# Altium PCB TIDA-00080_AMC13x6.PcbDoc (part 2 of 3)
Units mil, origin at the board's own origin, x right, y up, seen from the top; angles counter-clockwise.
Board outline 7283.46 x 2559.06 mil, 4 copper layers (Top Layer, MidLayer1, MidLayer2, Bottom Layer), stack 61.2 mil thick; 372 components, 160 nets, 901 pads, 256 vias.
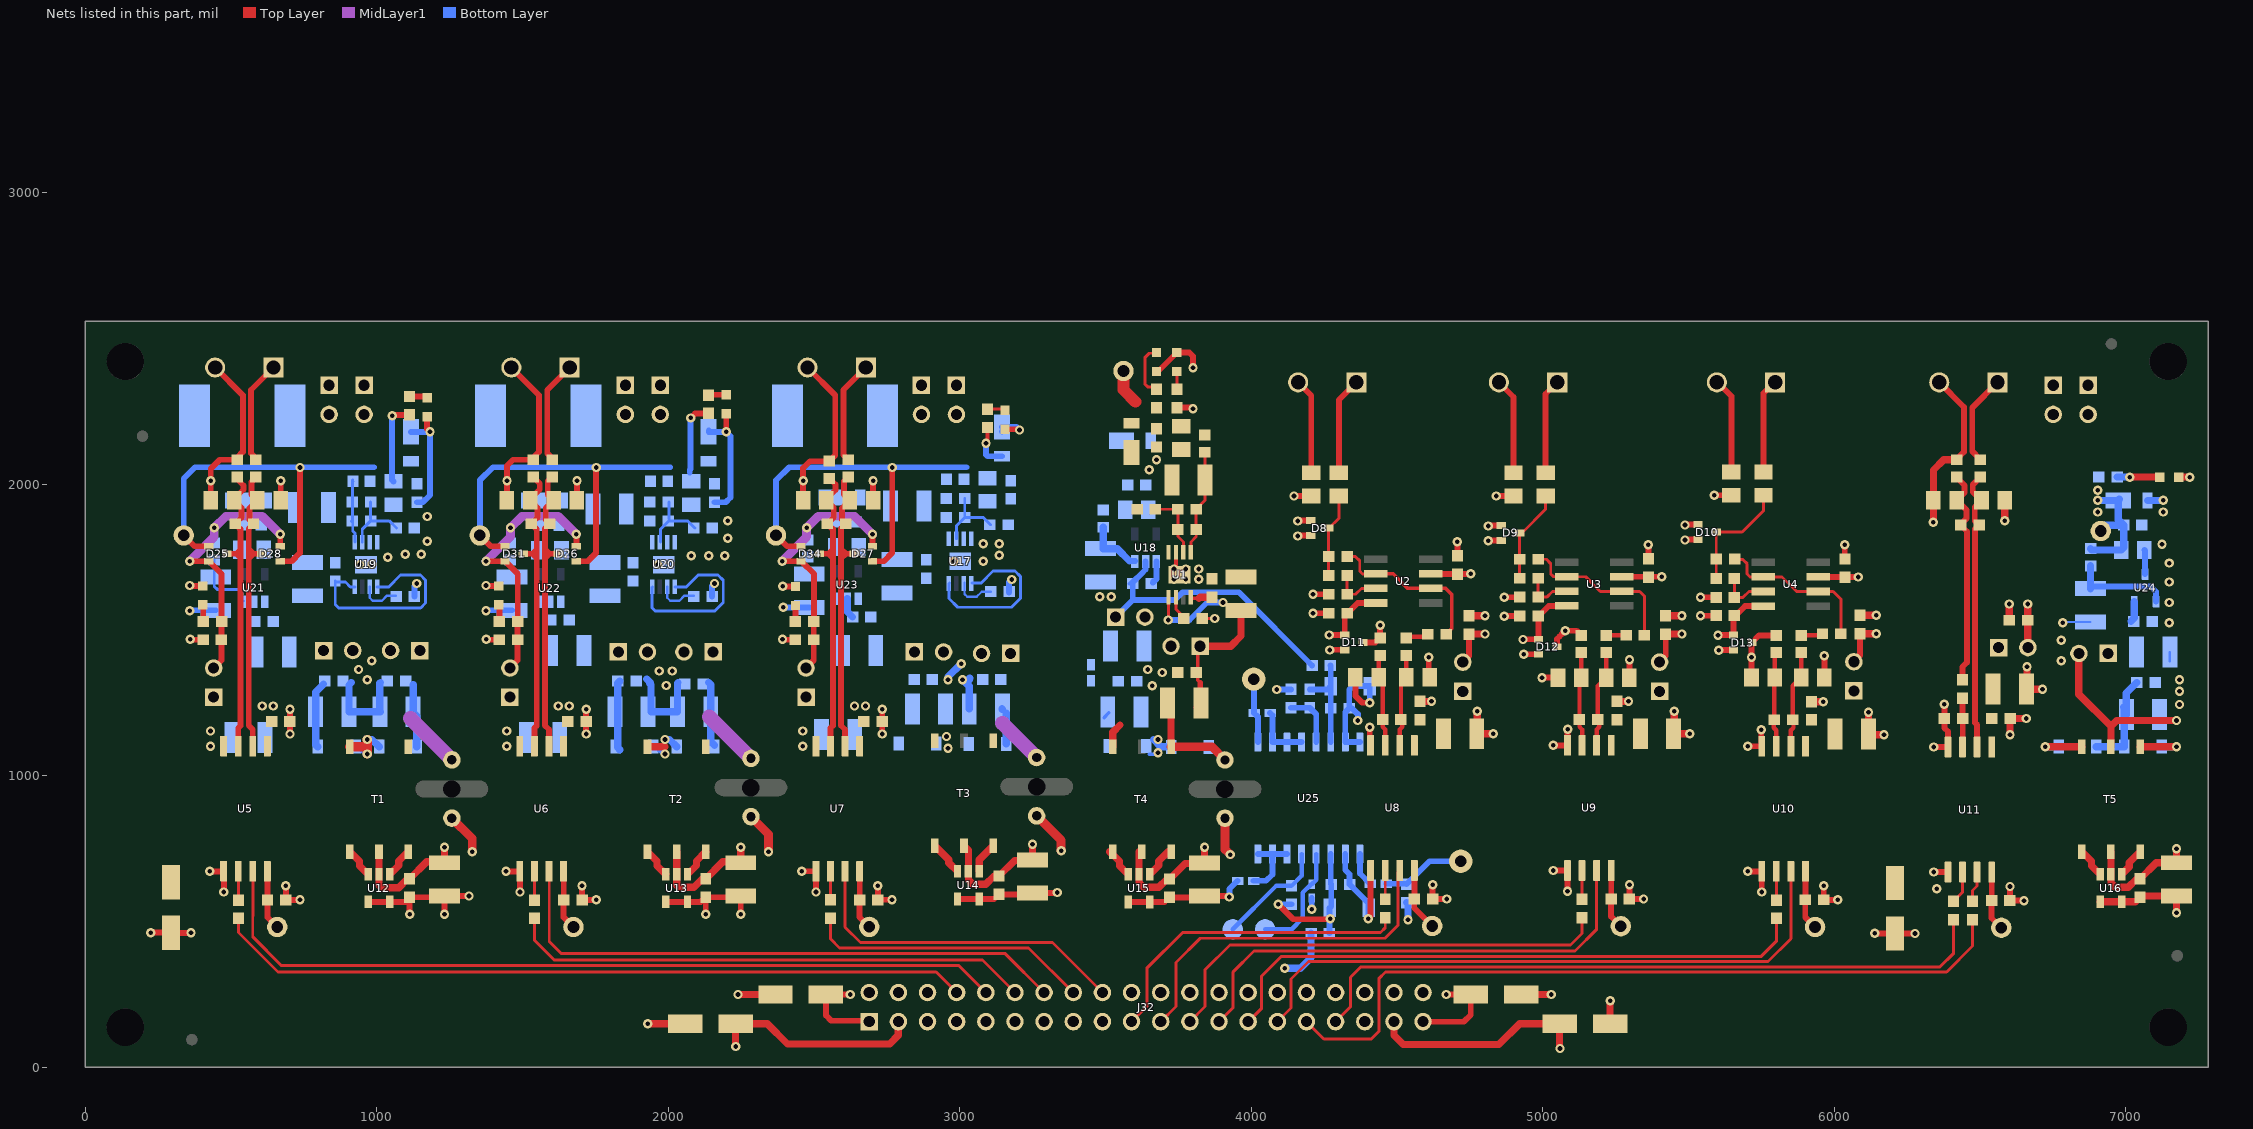
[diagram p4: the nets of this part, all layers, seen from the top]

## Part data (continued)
U12 U13 U14 U15 U16: "Transformer Driver for Isolated Power Supplies, DBV0005A", Alternate Manufacturer=None, Manufacturer="Texas Instruments"
U18 U21 U22 U23: "Regulator, LDO, 5V, 0.15A, SOT23-5", Alternate Manufacturer=None, Manufacturer="Texas Instruments"
U19: "-36V, -200mA, Ultralow-Noise, Negative Linear Regulator", Alternate Manufacturer=None, Manufacturer="Texas Instruments"
U24: library part CMP-0074892-1, "100-mA, 30-V, Fixed-Output, Linear-Voltage Regulator, DBZ0003A (SOT-23-3)", Alternate Manufacturer="Texas Instruments", Alternate PartNumber=TLV76050DBZT
U25: library part CMP-0081958-3, "500 mW, High-Efficiency, Low-Emissions, 5 kVRMS Isolated DC-DC Converter, DVE0016A (SO-MOD-16)", Alternate Manufacturer="Texas Instruments", Alternate PartNumber=UCC12050DVE, Operating Temperature Range="-40 to 125 C"
ZZ1: library part AssemblyNoteLabel, Alternate Manufacturer=-
ZZ2 ZZ3 ZZ4: library part AssemblyNote, Alternate Manufacturer=-

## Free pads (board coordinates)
  oval 250x60 hole 60 slot 250 at 0 deg unplated mask+10: 0(1258,955) 0(2284,960) 0(3264,963) 0(3910.2,954.72)

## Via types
v1: diameter 32, hole 16, Top Layer to Bottom Layer, tented both sides, 256 vias

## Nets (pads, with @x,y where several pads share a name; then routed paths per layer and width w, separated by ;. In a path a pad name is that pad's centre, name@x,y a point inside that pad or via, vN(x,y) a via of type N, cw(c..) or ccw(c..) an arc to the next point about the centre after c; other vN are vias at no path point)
+3.3V_DVDD: C61.2 C62.2 C63.2 C64.2 C65.2 C66.2 C67.2 C80.1 C81.1 J32.1 J32.39 TP6.1 TP7.1 TP8.1 TP9.1 TP10.1 TP11.1 TP12.1 U5.8 U6.8 U7.8 U8.8 U9.8 U10.8 U11.8 | length 2085.5
  Top Layer w20: U5.8@626,672.5 626,575 C61.2@625.5,574.5 625.5,515 TP6.1@659,481.5 ; U6.8@1642,672.5 1642,575 C62.2@1641.5,574.5 1641.5,515 TP7.1@1675,481.5 ; v1(2624.72,250) C80.1@2541.34,250 2541.34,178.39 2559.72,160 2686.43,160 J32.1@2689.73,156.69 ; U7.8@2656.99,672.87 2656.99,575.36 C66.2@2656.5,574.87 2656.5,515.36 TP8.1@2689.99,481.87 ; U8.8@4559.89,675.51 4559.89,578.01 C67.2@4559.39,577.51 4559.39,546.61 TP9.1@4621,485 ; J32.39@4589.73,156.69 4729.72,156.69 4753.11,180.08 C81.1@4753.11,250 v1(4669.72,250) ; U9.8@5235.19,675.51 5235.19,578.01 C63.2@5234.7,577.51 5234.7,518.01 TP10.1@5268.19,484.51 ; U10.8@5901.5,672.5 C64.2@5901.5,575 5901.01,574.5 5901.01,515 TP11.1@5934.5,481.5 ; U11.8@6540.45,670 6540.45,572.5 C65.2@6539.95,572 6539.95,512.5 TP12.1@6573.45,479
+5.0V_PH: C22.2 C24.2 C26.2 C36.1 C39.1 C42.1 C87.1 C95.2 D8.2 D9.2 D10.2 D11.2 D12.2 D13.2 D18.1 FB11.2 J28.2 J29.2 J30.2 R2.2 U2.7 U3.7 U4.7 | length 1247.5
  Top Layer w20: R2.2@3745.2,2263.23 3798.7,2263.23 3800.2,2264.72 v1(3800.2,2259.72) ; v1@4161.59,1824.41 D8.2@4204.5,1824.41 ; v1(4269.89,1431.83) 4270.48,1432.42 D11.2@4320.89,1432.42 D11.2@4323.39,1432.42 ; U2.7@4616.38,1693.01 v1(4753.38,1693.01) ; J28.2@4725.89,1390.01 4746.89,1411.01 C36.1@4746.89,1486.51 ; v1@4815.29,1807.8 D9.2@4858.2,1807.8 ; v1(4935.19,1416.83) 4935.78,1417.42 D12.2@4986.19,1417.42 ; D12.2@4985.6,1418.01 D12.2@4986.19,1417.42 ; D12.2@4988.7,1417.42 D12.2@4986.19,1417.42 ; U3.7@5271.69,1683.01 v1(5408.69,1683.01) ; J29.2@5401.19,1390.01 5422.19,1411.01 C39.1@5422.19,1486.51 ; v1@5489.61,1810.8 D10.2@5532.52,1810.8 ; v1(5604.01,1431.32) 5604.6,1431.91 D13.2@5655.01,1431.91 ; D13.2@5654.42,1432.5 D13.2@5655.01,1431.91 ; D13.2@5657.51,1431.91 D13.2@5655.01,1431.91 ; U4.7@5945.5,1682.5 v1(6082.5,1682.5) ; J30.2@6067.5,1391.5 6088.5,1412.5 C42.1@6088.5,1488.01
  Top Layer w25: C36.1@4746.38,1486.01 C36.1@4746.89,1486.51 v1(4802.39,1486.51) ; C39.1@5421.69,1486.01 5422.19,1486.51 v1(5477.7,1486.51) ; C42.1@6088,1487.5 C42.1@6088.5,1488.01 v1(6144.01,1488.01)
  other v1: 4813.79,1806.3 5488.11,1809.3 4160.09,1822.91
+5.0V_USH: C32.1 C96.1 C102.2 D21.1 D25.2 D28.2 FB12.2 J26.2 R28.2 | length 920.5
  Top Layer w20: v1(359,1736) 425,1736 468,1693 R28.2@468,1530 467.5,1529.5 C32.1@467.5,1467 467.5,1396.5 J26.2@441,1370 ; D28.2@668.99,1787.59 v1(669,1829)
  MidLayer1 w30: v1(359,1736) 443,1820 v1(443,1851) 483,1891 607,1891 v1(669,1829)
+5.0V_VDC: C45.1 C101.1 C106.2 D24.1 FB15.2 J31.2 R60.2 TP2.1 | length 576.4
  Top Layer w25: v1(6663.94,1589.5) C45.1@6663.94,1534 6664.45,1533.5 J31.2@6664.45,1440
  Bottom Layer w25: FB15.2@6879.45,1779.53 6883.98,1775 C106.2@6984.45,1775 6992.95,1783.5 C101.1@6992.95,1860 ; v1(6904.45,1945) D24.1@6974.25,1945 ; TP2.1@6929.45,1860 C101.1@6992.95,1860 ; D24.1@6977.95,1948.7 D24.1@6974.25,1945 ; D24.1@6974.25,1945 6974.25,1878.7 C101.1@6992.95,1860
  other v1: 6904.45,1905 6904.45,1980
+5.0V_VSH: C33.1 C98.1 C103.2 D22.1 D26.2 D31.2 FB13.2 J27.2 R30.2 | length 920.5
  Top Layer w20: v1(1375,1736) 1441,1736 1484,1693 R30.2@1484,1530 1483.49,1529.5 C33.1@1483.49,1467 1483.49,1396.5 J27.2@1457,1370 ; D26.2@1684.99,1787.59 v1(1685,1829)
  MidLayer1 w30: v1(1375,1736) 1459,1820 v1(1459,1851) 1499,1891 1623,1891 v1(1685,1829)
+5.0V_WSH: C34.1 C100.1 C104.2 D23.1 D27.2 D34.2 FB14.2 J22.2 R32.2 | length 920.5
  Top Layer w20: v1(2390.99,1736) 2456.99,1736 2499.99,1693 2499.99,1530 R32.2@2499.49,1529.5 C34.1@2499.49,1467 2499.49,1396.5 J22.2@2472.99,1370 ; D27.2@2700.98,1787.59 v1(2700.98,1828.99)
  MidLayer1 w30: v1(2390.99,1736) 2474.98,1819.99 v1(2474.98,1850.99) 2514.98,1890.99 2638.98,1890.99 v1(2700.98,1828.99)
+5V_CNTL: C68.1 C69.2 C70.2 C71.2 C72.2 C73.2 C74.2 C75.2 C76.2 C77.2 C78.2 C79.1 C82.1 C83.1 J32.3 J32.37 R33.2 R35.2 T1.2 T2.2 T3.2 T4.2 T5.2 U12.2 U13.2 U14.2 U15.2 U16.2 | length 4137.8
  Top Layer w20: v1(225,462.28) 293.61,462.28 C79.1@294.39,461.5 v1(363,461.5) ; v1(6139.45,459.77) 6208.06,459.77 C68.1@6208.45,459.39 6208.83,459 v1(6277.45,459)
  Top Layer w25: T1.2@1008,740 U12.2@1008,662.24 1008,625 1016.44,616.56 1075.85,616.56 1104.29,645 C71.2@1108,645 ; C71.2@1113,646.5 1171.5,705 C72.2@1233,705 ; C72.2@1233,702.09 C72.2@1233,705 ; v1(1233,755) C72.2@1233,705 ; T2.2@2029,740 U13.2@2029,662.24 2029,625 2035.91,618.09 2088.52,618.09 2116.92,646.5 C73.2@2129,646.5 2187.5,705 C74.2@2249,705 ; v1(2231.34,71.61) C82.1@2231.34,150 2339.72,150 2409.72,80 2759.72,80 2789.73,110.01 J32.3@2789.73,156.69 ; C74.2@2249,702.09 C74.2@2249,705 ; v1(2249,755) C74.2@2249,705 ; T3.2@3015,760 3030,745 U14.2@3030,672.24 3030,643.38 3045.28,628.09 3089.51,628.09 3117.92,656.5 C75.2@3131.49,656.5 ; C75.2@3135,660 C75.2@3131.49,656.5 ; C76.2@3250,710 3188.5,710 C75.2@3135,656.5 C75.2@3131.49,656.5 ; C76.2@3250,712.09 v1(3250,765) ; T4.2@3615.2,739.72 U15.2@3615.2,661.97 3615.2,634.72 3617.31,632.62 3617.31,630.99 3630.49,617.81 3683.29,617.81 3711.7,646.22 C77.2@3720.2,646.22 3773.7,699.72 C78.2@3840.2,699.72 ; C78.2@3840.2,701.81 v1(3840.2,754.72) ; J32.37@4489.73,156.69 4489.73,109.99 4521.34,78.39 4849.72,78.39 4921.34,150 C83.1@5058.11,150 5058.11,66.61 v1(5059.72,65) ; T5.2@6949.45,740 U16.2@6949.45,662.24 6949.45,633.38 6964.74,618.09 7008.97,618.09 7037.37,646.5 C69.2@7049.45,646.5 7105.04,702.09 C70.2@7174.45,702.09 v1(7174.45,750)
  Bottom Layer w25: v1@2229.72,70 v1(2231.34,71.61) ; v1(4115,340) 4169.35,340 4205.5,376.16 R33.2@4205.5,460 ; R35.2@4533,565.5 4538,560.5 v1(4538,507)
+6V_PH: C112.1 C125.2 J16.1 R31.1 R34.2 U18.2 | length 965.9
  Bottom Layer w12: C112.1@3582.6,1658.98 C112.1@3591.11,1667.48
  Bottom Layer w20: J16.1@3535.2,1544.72 3593.7,1603.23 ; C112.1@3593.7,1659.72 3593.7,1603.23 ; C112.1@3597.6,1667.48 3624.41,1694.29 3624.41,1694.46 3637.6,1707.65 U18.2@3637.6,1735.24 ; R34.2@4208.92,1379 3957.92,1630 3764.2,1630 3737.43,1603.23 3593.7,1603.23
+6V_USH: C114.1 C126.2 C127.1 C138.1 D29.1 J18.1 U21.2 | length 229.2
  Bottom Layer w25: D29.1@798,1100 790.91,1107.09 C138.1@790.91,1220 790.91,1287.91 C127.1@818,1315
+6V_VDC: C124.1 C135.1 C136.2 C145.1 D39.1 D40.1 J25.1 U24.2 | length 429.4
  Bottom Layer w25: D39.1@6898.92,1100 D40.1@6994.98,1100 6994.98,1232.38 C145.1@6992.36,1235 ; C145.1@7002.36,1210 7002.36,1284.41 C135.1@7037.95,1320 ; C124.1@7017.95,1530 7029.45,1541.5 U24.2@7029.45,1597.76
+6V_VSH: C118.1 C129.2 C137.1 C140.1 D32.1 J20.1 U22.2 | length 240.9
  Bottom Layer w25: D32.1@1834,1090 1826.91,1097.09 1826.91,1317.91 C137.1@1834,1325
+6V_WSH: C122.1 C131.2 C132.1 C142.1 D35.1 J23.1 U23.2 | length 70.4
  Bottom Layer w25: U23.2@2614,1608.02 2614,1563.77 C122.1@2632.5,1545.27
-5.0V_PH: C1.2 C2.1 C29.2 C30.2 C31.2 D6.2 D8.1 D9.1 D10.1 D11.1 D12.1 D13.1 FB1.2 R1.2 TP1.1 U2.4 U3.4 U4.4 | length 971.9
  Top Layer w20: v1@4161.59,1875.59 D8.1@4204.5,1875.59 ; v1(4267.38,1483.01) 4267.97,1483.6 D11.1@4320.89,1483.6 4320.89,1548.35 C29.2@4329.71,1557.17 ; C29.2@4328.88,1558.01 C29.2@4329.71,1557.17 ; U2.4@4427.38,1593.01 4365.55,1593.01 C29.2@4329.71,1557.17 ; v1@4815.29,1858.98 D9.1@4858.2,1858.98 ; v1(4932.69,1468.01) 4933.28,1468.6 D12.1@4986.19,1468.6 4986.19,1546 C30.2@4984.19,1548.01 4985.86,1548.01 5020.86,1583.01 U3.4@5082.69,1583.01 ; v1@5489.61,1861.98 D10.1@5532.52,1861.98 ; v1(5601.5,1482.5) 5602.09,1483.09 D13.1@5655.01,1483.09 C31.2@5655.01,1547.5 ; C31.2@5659.67,1547.5 5694.67,1582.5 U4.4@5756.5,1582.5
  Top Layer w40: TP1.1@3562,2389 3562,2325 3603,2284
  other v1: 4813.79,1857.48 5488.11,1860.48 4160.09,1874.09
-5.0V_USH: C89.1 C90.2 D19.2 D25.1 D28.1 FB9.2 R3.2 TP3.1 | length 1627
  Top Layer w20: TP3.1@338,1825 375.41,1787.59 D25.1@424.01,1787.59 ; D28.1@668.99,1736.41 708.41,1736.41 737,1765 v1(737,2058) ; v1(1053,2235) 1056.5,2238.5 R3.2@1113,2238.5
  Bottom Layer w20: TP3.1@338,1825 338,2020 377,2059 991,2059 ; v1(1053,2235) 1053,2015 C90.2@1058,2010
-5.0V_VSH: C92.2 C93.1 D20.2 D26.1 D31.1 FB10.2 R4.2 TP4.1 | length 1592.5
  Top Layer w20: TP4.1@1354,1825 1391.41,1787.59 D31.1@1440,1787.59 ; D26.1@1684.99,1736.41 1724.41,1736.41 1753,1765 v1(1753,2058) ; v1(2077,2228) 2092.5,2243.5 R4.2@2139,2243.5
  Bottom Layer w20: TP4.1@1354,1825 1354,2014 1399,2059 2007,2059 ; 2074,2040.2 2074,2050 2077,2053 v1(2077,2228)
-5.0V_WSH: C85.2 C86.1 D17.2 D27.1 D34.1 FB8.2 R5.2 TP5.1 | length 1488.6
  Top Layer w15: v1@3091.89,2140.1 3095.4,2143.61 R5.2@3095.4,2195.1
  Top Layer w20: TP5.1@2369.99,1825 2407.4,1787.59 D34.1@2456,1787.59 ; D27.1@2700.98,1736.41 2740.39,1736.4 2768.98,1764.99 v1(2768.98,2057.99)
  Bottom Layer w20: TP5.1@2369.99,1825 2369.99,2014 2415,2059 3022.99,2059 ; v1(3090.4,2141.6) 3090.4,2101.6 3095.59,2096.4 D17.2@3145.4,2096.4
-6V_PH: C20.1 C28.2 C35.2 C49.2 D38.2 J17.1 U1.5 U1.8 | length 824.9
  Top Layer w10: v1(3715.2,1534.72) 3716.4,1535.92 U1.5@3716.4,1613.12
  Top Layer w12: U1.8@3793.2,1613.12 3796.6,1609.72 3821.1,1609.72 3821.1,1610.62 ; 3825.2,1319.72 3817.29,1327.64 3817.29,1444.72 J17.1@3825.2,1444.72
  Top Layer w20: C49.2@3811.7,1234.72 3825.2,1248.23 3825.2,1319.72
  Top Layer w25: 3821.1,1609.72 3824.6,1613.23 C20.1@3865.2,1613.23 ; J17.1@3825.2,1444.72 3930.2,1444.72 3965.2,1479.72 C28.2@3965.2,1562.64
  Bottom Layer w12: 3835.2,1094.72 D38.2@3837.29,1096.81
  Bottom Layer w20: v1@3725.2,1534.72 3788.79,1534.72 3848.72,1594.65 v1(3903.5,1594.65)
-6V_USH: C107.2 C115.1 C128.2 C139.2 D30.2 J19.1 U19.5 U19.8 | length 963.8
  Bottom Layer w10: C115.1@858,1668.5 C115.1@858,1665 ; U19.8@925,1648.4 909.6,1648.4 893,1665 C115.1@858,1665 ; U19.5@1001.8,1648.4 1041.4,1648.4 1082,1689 1150.01,1689 1168,1671.01 1168,1593 1151,1576 870,1576 858,1588 C115.1@858,1665
  Bottom Layer w25: C139.2@1123,1220 1137.47,1205.53 D30.2@1137.47,1100 ; C139.2@1125.09,1220 1125.09,1312.91
-6V_VSH: C108.2 C119.1 C130.2 C141.2 D33.2 J21.1 U20.5 U20.8 | length 823.8
  Bottom Layer w10: U20.8@1946,1648.4 1944,1646.4 1944,1578 1957,1565 2159,1565 2189,1595 2189,1671.01 2171.01,1689 2103,1689 2062.4,1648.4 U20.5@2022.8,1648.4
  Bottom Layer w25: C130.2@2139,1320 2146.09,1312.91 C141.2@2146.09,1220 2146.09,1117.91 D33.2@2159,1105
-6V_WSH: C105.1 C109.2 C133.2 C143.2 D36.2 J24.1 U17.5 U17.8 | length 697.6
  Bottom Layer w10: U17.8@2965.2,1662 U17.8@2963.2,1660 2963.2,1608.6 2993.2,1578.6 3178.2,1578.6 3208.2,1608.6 3208.2,1684.61 3190.21,1702.6 3114.6,1702.6 3074,1662 U17.5@3042,1662
  Bottom Layer w25: C143.2@3145,1230 C143.2@3146.04,1228.96 ; D36.2@3159.46,1110 C143.2@3159.46,1215.53
CLKN_CH_U: J32.9
CLKN_CH_V: J32.13
CLKN_CH_W: J32.17
CLKN_U_PH: J32.22
CLKN_V_PH: J32.26
CLKN_VDC: J32.34
CLKN_W_PH: J32.30
CLKP_CH_U: J32.10 U5.7 | length 2971.8
  Top Layer w10: U5.7@575,672.87 575,448 674,349 2997.43,349 J32.10@3089.73,256.69 ; 576,519.5 U5.7@576,672.5
CLKP_CH_V: J32.14 U6.7 | length 2010.9
  Top Layer w10: U6.7@1592,672.5 1592,432 1634,390 3156.43,390 J32.14@3289.73,256.69
CLKP_CH_W: J32.18 U7.7 | length 1167.5
  Top Layer w10: U7.7@2606.99,672.87 2606.99,481.01 2660,428 3318.43,428 J32.18@3489.73,256.69
CLKP_U_PH: J32.21 U8.7 | length 1230.1
  Top Layer w10: J32.21@3689.73,156.69 3742,208.96 3742,360 3825,443 4459.37,443 4504,487.63 4504,669.63 U8.7@4509.89,675.51
CLKP_V_PH: J32.25 U9.7 | length 1700.2
  Top Layer w10: J32.25@3889.73,156.69 3937,203.96 3937,326 4010,399 5110.68,399 5185.19,473.51 U9.7@5185.19,675.51
CLKP_VDC: J32.33 R25.1 | length 2392.2
  Top Layer w10: J32.33@4289.73,156.69 4341,207.96 4341,309 4377,345 6363.45,345 6410,391.55 R25.1@6410,507.01
CLKP_W_PH: J32.29 U10.7 | length 2168.8
  Top Layer w10: J32.29@4089.73,156.69 4137,203.96 4137,303 4197,363 5773,363 5851.5,441.5 U10.7@5851.5,672.5
DGND: C57.1 C58.1 C59.1 C60.1 C61.1 C62.1 C63.1 C64.1 C65.1 C66.1 C67.1 C68.2 C69.1 C70.1 C71.1 C72.1 C73.1 C74.1 C75.1 C76.1 C77.1 C78.1 C79.2 C80.2 C81.2 C82.2 C83.2 C150.1 C154.2 J32.2 J32.4 J32.5 J32.6 J32.35 J32.36 J32.38 J32.40 R41.1 R44.2 U5.5 U6.5 U7.5 U8.5 U9.5 U10.5 U11.5 U12.4 U12.5 U13.4 U13.5 U14.4 U14.5 U15.4 U15.5 U16.4 U16.5 U25.2 | length 4763.7
  Top Layer w20: v1(427.5,672.5) 476,672.5 v1(476,601.5) ; v1(688.5,623.01) C61.1@688.5,574.5 v1(737,574.5) ; U12.4@970.6,567.76 U12.5@1045.4,567.76 1100.76,567.76 C71.1@1113,580 ; v1(1113,525) C71.1@1113,580 ; C72.1@1228,585 1226.5,583.5 C71.1@1113,583.5 C71.1@1113,580 ; v1(1233,525) C72.1@1233,587.91 1233.09,588 v1(1317,588) ; C72.1@1235.91,582.91 C72.1@1237.41,581.42 ; v1(1443.49,672.5) 1492,672.5 v1(1492,601.5) ; v1(1704.49,623.01) C62.1@1704.49,574.5 v1(1753,574.5) ; U13.4@1991.6,567.76 2061.24,567.76 U13.5@2064,565 ; U13.5@2066.4,567.76 2111.76,567.76 C73.1@2129,585 ; v1(2129,525) C73.1@2129,583.5 C74.1@2249,583.5 ; v1(2249,525) C74.1@2249,583.5 ; C74.1@2249,587.91 C74.1@2249,583.5 ; v1(2458.49,672.87) U7.5@2506.99,672.87 v1(2506.99,601.87) ; v1(2719.49,623.37) C66.1@2719.49,574.87 v1(2767.99,574.87) ; U14.4@2992.59,577.76 3062.75,577.76 U14.5@3065,580 ; U14.5@3067.4,577.76 3117.75,577.76 C75.1@3135,595 ; C75.1@3135,593.5 3253.5,593.5 C76.1@3255,595 ; C76.1@3250,597.91 3332.91,597.91 v1(3335,600) ; U15.4@3577.8,567.48 3647.96,567.48 U15.5@3650.2,569.72 ; U15.5@3652.6,567.48 3702.96,567.48 C77.1@3720.2,584.72 ; C77.1@3720.2,583.23 3838.7,583.23 C78.1@3840.2,584.72 ; C78.1@3840.2,587.64 3922.29,587.64 v1(3925.2,584.72) ; v1(4402,510) 4409.89,517.89 U8.5@4409.89,675.51 ; v1(4622.38,626.02) C67.1@4622.38,577.51 v1(4670.89,577.51) ; v1(5036.69,675.51) U9.5@5085.19,675.51 v1(5085.19,604.51) ; v1(5297.69,626.02) C63.1@5297.69,577.51 v1(5346.19,577.51) ; v1(5703,672.5) U10.5@5751.5,672.5 v1(5751.5,601.5) ; v1(5964,623.01) 5964,574.5 v1(6012.5,574.5) ; v1(6341.94,670) U11.5@6390.45,670 ; v1(6602.94,620.5) C65.1@6602.94,572 v1(6651.45,572)
  Top Layer w25: v1(1929.72,150) C82.2@2058.11,150 ; v1(2239.72,250) C80.2@2368.11,250 ; C81.2@4926.34,250 v1(5029.72,250) ; C83.2@5231.34,150 v1(5231.34,228.39) ; U16.4@6912.05,567.76 U16.5@6986.85,567.76 7033.7,567.76 C69.1@7049.45,583.5 7053.86,587.91 C70.1@7174.45,587.91 v1(7174.45,530)
  Top Layer w30: C57.1@1258,855 1328,785 v1(1328,740) ; C58.1@2284,860 2344,800 v1(2344,740) ; C59.1@3264,863 3348,779 v1(3348,743) ; C60.1@3910.2,854.72 3910.2,747.8 v1(3928,730)
  Bottom Layer w20: v1(3925.2,584.72) 3925.2,611.76 R44.2@3953.44,640 ; v1(4208,542) R41.1@4208,580.89 ; U25.2@4323,732.07 4323,677 4337.5,662.5 C150.1@4337.5,628 4402.93,562.57 C154.2@4402.93,547 4402.93,509.93 4402.86,510 v1(4402,510)
  other v1: 6352,613
DOUTN_CH_U: J32.7
DOUTN_CH_V: J32.11
DOUTN_CH_W: J32.15
DOUTN_U_PH: J32.20
DOUTN_V_PH: J32.24
DOUTN_VDC: J32.32
DOUTN_W_PH: J32.28
DOUTP_CH_U: J32.8 R39.2 | length 2597.2
  Top Layer w10: R39.2@526,511.01 526,463 662,327 2919.43,327 J32.8@2989.73,256.69
DOUTP_CH_V: J32.12 R42.2 | length 1797.6
  Top Layer w10: R42.2@1542,511.01 1542,435 1609,368 3078.43,368 J32.12@3189.73,256.69
DOUTP_CH_W: J32.16 R46.2 | length 979.4
  Top Layer w10: R46.2@2556.99,511.37 2556.99,441.01 2588,410 3236.43,410 J32.16@3389.73,256.69
DOUTP_U_PH: J32.19 R48.2 | length 1115.5
  Top Layer w10: J32.19@3589.73,156.69 3642,208.96 3642,340 3765,463 4444,463 4459.89,478.89 R48.2@4459.89,514.02
DOUTP_V_PH: J32.23 R51.2 | length 1599.2
  Top Layer w10: J32.23@3789.73,156.69 3842,208.96 3842,335 3927,420 5095.68,420 5135.19,459.51 R51.2@5135.19,514.02
DOUTP_VDC: J32.31 R58.2 | length 2638.5
  Top Layer w10: J32.31@4189.73,156.69 4249.23,97.19 4412.19,97.19 4438,123 4438,304 4461,327 6386,327 6475,416 R58.2@6475,506.5
DOUTP_W_PH: J32.27 R55.2 | length 2069
  Top Layer w10: J32.27@3989.73,156.69 4036,202.96 4036,313 4104,381 5750,381 5801.5,432.5 R55.2@5801.5,511.01
GND_PH: C1.1 C2.2 C9.1 C20.2 C21.2 C22.1 C23.2 C24.1 C25.2 C26.1 C27.1 C28.1 C29.1 C30.1 C31.1 C35.1 C36.2 C37.1 C38.1 C39.2 C40.1 C41.1 C42.2 C43.1 C44.1 C49.1 C50.2 C52.2 C54.2 C60.2 C87.2 C95.1 C111.1 C112.2 C125.1 C134.2 C144.2 C147.1 C148.1 C149.1 C152.1 C155.1 D1.2 D2.1 D6.1 D11.3 D12.3 D13.3 D18.2 FB19.1 FB21.1 FB23.1 J16.2 J17.2 R8.2 R11.2 R14.1 R19.2 R43.1 R45.1 T4.4 TP16.1 U1.3 U1.4 U1.9 U8.4 U9.4 U10.4 U18.1 U25.9 U25.15 U25.16 | length 3942.5
  Top Layer w10: C27.1@3831.7,1539.72 v1(3875.2,1539.72)
  Top Layer w15: U1.9@3742,1702.12 U1.3@3742,1766.72
  Top Layer w20: D1.2@3675.2,2387.24 3680.24,2387.24 D2.1@3745.2,2452.2 3787.72,2452.2 3800.2,2439.72 v1(3800.2,2399.72) ; U1.9@3742,1702.12 U1.9@3754.4,1689.72 ; v1(4147,1960) R8.2@4206,1960 R8.2@4208,1958 ; v1(4212.38,1558.01) C29.1@4265.89,1558.01 ; v1(4212.38,1623.01) C21.2@4265.89,1623.01 ; C37.1@4357.38,1338.01 4357.38,1274.62 4380.93,1251.07 v1(4406.93,1251.07) ; D11.3@4383.88,1458.01 4425.89,1458.01 FB19.1@4440.41,1472.54 ; v1(4407,1167) 4407,1107.53 U8.4@4409.89,1104.65 U8.4@4410.38,1105.14 ; v1(4442.38,1517.01) FB19.1@4442.38,1474.5 ; C38.1@4609.38,1346.01 v1(4609.38,1407.01) ; C22.1@4707.38,1754.5 v1(4707.38,1803.01) ; v1(4841,1960) R11.2@4900,1960 R11.2@4902,1958 ; v1(4867.69,1548.01) C30.1@4921.19,1548.01 ; v1(4867.69,1613.01) C23.2@4921.19,1613.01 ; v1(4997.69,1337.01) C40.1@5052.69,1337.01 C40.1@5052.69,1323.01 ; v1(5036.69,1104.65) U9.4@5085.19,1104.65 5085.69,1105.14 v1(5085.69,1160.01) ; D12.3@5049.19,1443.01 5049.19,1469.5 ; 5057.89,1478.21 5049.19,1469.5 ; FB21.1@5132.67,1481.8 5116.47,1498.01 v1(5077.69,1498.01) 5049.19,1469.5 ; C41.1@5297.69,1323.01 C41.1@5297.69,1337.01 v1(5297.69,1398.01) ; C24.1@5362.69,1744.5 v1(5362.69,1793.01) ; v1(5541.5,1549.5) C31.1@5595.01,1549.5 ; v1(5541.5,1612.5) C25.2@5595.01,1612.5 ; v1(5588.52,1962.5) R19.2@5647.52,1962.5 R19.2@5649.52,1960.5 ; v1(5703,1101.64) U10.4@5751.5,1101.64 5750,1103.14 v1(5750,1158) ; C43.1@5716.5,1337.5 v1(5716.5,1407.5) 5716.5,1457.5 D13.3@5717.25,1458.25 ; D13.3@5718,1457.5 5742.53,1482.03 FB23.1@5801.5,1482.03 ; C44.1@5966.5,1337.5 v1(5966.5,1412.5) ; C26.1@6036.5,1744 v1(6036.5,1792.5) ; FB19.1@4440.41,1472.54 FB19.1@4442.38,1474.5 ; FB19.1@4440.41,1472.54 FB19.1@4442.38,1472.54 FB19.1@4442.38,1474.5
  Top Layer w25: C49.1@3713.11,1249.72 3725.2,1237.64 T4.4@3725.2,1099.57 ; C50.2@4579.38,1255.5 v1(4618.89,1255.5) ; C36.2@4746.89,1549.5 v1(4802.39,1549.5) ; v1(4775.97,1221.3) 4775.97,1146.51 C147.1@4773.98,1144.52 v1@4829.49,1144.52 ; C52.2@5254.69,1255.5 v1(5294.19,1255.5) ; C39.2@5422.19,1549.5 v1(5477.7,1549.5) ; v1(5451.28,1221.3) 5451.28,1146.51 C148.1@5449.29,1144.52 v1(5504.79,1144.52) ; C54.2@5922.5,1255 5923,1254.5 v1(5962.5,1254.5) ; C42.2@6088.5,1551 v1(6144.01,1551) ; v1(6117.59,1218.29) C149.1@6117.59,1143.5 6115.6,1141.51 v1(6171.1,1141.51)
  Top Layer w30: T4.4@3725.2,1099.57 3865.36,1099.57 C60.2@3910.2,1054.72
  Bottom Layer w20: C112.2@3662.6,1662.48 C112.2@3664.1,1663.98 ; C112.2@3664.1,1667.48 C112.2@3664.1,1663.98 ; U18.1@3675,1735.24 3675,1674.88 C112.2@3664.1,1663.98 ; TP16.1@4009,1332 4009.88,1331.12 R45.1@4009.88,1216 4023,1202.88 U25.9@4023,1115.93 ; v1(4087.5,1296.5) R43.1@4137,1296.5 ; v1(4366,1190) 4366,1211.79 4345.79,1232 C152.1@4336.5,1232 ; U25.16@4373,1115.93 U25.15@4323,1115.93 4323,1218.5 C152.1@4336.5,1232 ; v1(4406.93,1251.07) C155.1@4406.93,1308 4349,1308 4336.5,1295.5 C152.1@4336.5,1232
  other v1: 4831,1144.52 3660.2,1309.72 3695.2,1354.72 3645.2,1364.72 3480.2,1614.72 3520.2,1614.72 3735.2,1674.72 3775.2,1674.72 3820.2,1674.72 3735.2,1709.72 3775.2,1709.72 3820.2,1709.72 3650.2,2049.72 3675.2,2084.72
GND_USH: C57.2 C88.1 C89.2 C90.1 C96.2 C102.1 C107.1 C113.1 C114.2 C115.2 C116.1 C126.1 C127.2 C128.1 C138.2 C139.1 D4.2 D14.1 D19.1 D21.2 J1.1 J1.2 J18.2 J19.2 R64.1 T1.4 U19.3 U19.4 U19.9 U21.1 | length 1089
  Top Layer w20: v1(359,1653) 360.52,1651.48 D14.1@403,1651.48 ; D4.2@1173,2232.52 1173,2190 v1(1183,2180)
  MidLayer1 w50: 1116,1197 C57.2@1258,1055
  Bottom Layer w20: v1@358.91,1567.91 C113.1@448,1567.91 ; D19.1@1118,2180.2 1182.8,2180.2 v1(1183,2180) 1183,1963 1158.5,1938.5 C89.2@1138,1938.5 ; C116.1@1129.5,1615 1129.5,1651.5 v1(1138,1660)
  Bottom Layer w25: 913,1320 905.09,1312.09 C138.2@905.09,1220 C139.1@1010.91,1220 ; C139.1@1013,1220 C139.1@1010.91,1220 ; 1013,1320 1010.91,1317.91 C139.1@1010.91,1220
  other v1: 968,1330 938,1365 983,1395 359,1566 943,1725 983,1725 1038,1750 1098,1760 1153,1760 1173,1805 1173,1890
GND_USH1: C3.1 C4.2 C17.1 C32.2 C46.2 FB3.1 J2.1 J2.2 J9.2 R20.1 U5.4 | length 780.4
  Top Layer w20: v1(360.5,1468.52) 362.02,1467 C32.2@404.5,1467 ; C3.1@431,1945 v1(431,2013) 431,2054 461.53,2084.53 FB3.1@521,2084.53 FB3.1@521,2091.5 ; J9.2@446,2401 541,2306 541,2111.5 FB3.1@521,2091.5 ; FB3.1@516,2086.5 FB3.1@521,2091.5 ; C4.2@671,1945 v1(671,2013) ; v1(702.5,1143.5) C46.2@702.5,1186 v1(702.5,1228.5)
  other v1: 430,1102 430,1154
GND_VDC: C101.2 C106.1 C123.1 C124.2 C135.2 C136.1 C145.2 D7.1 D24.2 J8.1 J8.2 J25.2 T5.5 U24.3 | length 903.4
  Top Layer w25: J25.2@6839.45,1420 6839.45,1280 6949.45,1170 ; T5.5@6949.45,1099.84 6949.45,1170 ; v1(7174.45,1190) 6969.45,1190 6949.45,1170 ; D7.1@7181.93,2025 v1(7219.45,2025)
  Bottom Layer w8: v1(6784.45,1525) 6787.36,1527.91 C123.1@6879.45,1527.91 ; C136.1@7151.54,1392.91 C136.1@7151.54,1425
  Bottom Layer w20: C106.1@7064.45,1775 7066.85,1772.6 U24.3@7066.85,1692.24
  Bottom Layer w25: D24.2@7074.65,1945 v1(7129.45,1945)
  other v1: 7184.45,1245 7184.45,1290 7184.45,1330 6779.45,1395 6779.45,1465 7149.45,1525 7149.45,1595 7149.45,1665 7149.45,1730 7124.45,1795 7129.45,1905
GND_VSH: C58.2 C91.1 C92.1 C93.2 C98.2 C103.1 C108.1 C117.1 C118.2 C119.2 C120.1 C129.1 C130.1 C137.2 C140.2 C141.1 D5.2 D15.1 D20.1 D22.2 J3.1 J3.2 J20.2 J21.2 R65.1 T2.4 U20.3 U20.4 U20.9 U22.1 | length 1123.8
  Top Layer w8: J20.2@1929,1400 J20.2@1929,1425
  Top Layer w20: v1(1375,1653) 1376.52,1651.48 D15.1@1419,1651.48 ; v1@2199,2195 D5.2@2199,2242.52
  MidLayer1 w50: 2140.5,1203.5 C58.2@2284,1060
  Bottom Layer w20: v1@1374.91,1567.91 C117.1@1464,1567.91 ; D20.1@2139,2185 D20.1@2139,2180.2 2198.8,2180.2 v1(2199,2180) 2214,2165 2214,1955 2197.5,1938.5 C93.2@2159,1938.5 ; C120.1@2150.5,1615 2150.5,1651.5 v1(2159,1660)
  Bottom Layer w25: 1926.91,1332.09 1939,1320 ; 1936.5,1317.5 1941.09,1312.91 1941.09,1220 C141.1@2031.91,1220 2031.91,1317.91 2034,1320
  other v1: 1994,1310 1969,1360 2014,1360 1375,1566 1964,1725 2079,1755 2139,1755 2194,1755 2204,1815 2204,1875
GND_VSH1: C5.1 C6.2 C18.1 C33.2 C47.2 FB5.1 J4.1 J4.2 J10.2 R22.1 U6.4 | length 772.3
  Top Layer w20: v1(1376.5,1468.52) 1378.02,1467 C33.2@1420.5,1467 ; C5.1@1447,1945 v1(1447,2013) 1447,2064 1467.53,2084.53 FB5.1@1537,2084.53 ; J10.2@1462,2401 1557,2306 1557,2111.5 FB5.1@1537,2091.5 ; C6.2@1687,1945 v1(1687,2013) ; v1(1718.49,1143.5) C47.2@1718.49,1186 v1(1718.49,1228.5)
  other v1: 1446,1102 1446,1154
GND_WSH: C59.2 C84.1 C85.1 C86.2 C100.2 C104.1 C105.2 C109.1 C110.1 C121.1 C122.2 C131.1 C132.2 C133.1 C142.2 C143.1 D3.2 D16.1 D17.1 D23.2 J5.1 J5.2 J23.2 J24.2 R63.1 T3.4 U17.3 U17.4 U17.9 U23.1 | length 664
  Top Layer w20: v1@2394.52,1649.47 D16.1@2437,1649.47 ; D3.2@3155.4,2189.12 3202.88,2189.12 v1(3205.4,2186.6)
  MidLayer1 w50: 3147,1180 C59.2@3264,1063
  Bottom Layer w20: v1(2394.91,1578.18) C121.1@2484,1578.18 ; D17.1@3145.4,2181.6 D17.1@3155.4,2191.6 ; D17.1@3145.4,2196.8 3195.2,2196.8 v1(3205.4,2186.6) ; C110.1@3169.69,1628.6 C110.1@3169.69,1631.9 3169.69,1665.1 v1(3178.2,1673.6)
  Bottom Layer w25: v1(2960,1330) 2960,1340 v1(3005,1385) ; v1(3010,1330) 3032.91,1307.09 C143.1@3032.91,1230 ; 3032.91,1330 3032.91,1332.91 3035,1335
  other v1: 2393,1650.99 2980.4,1736.6 3080.4,1736.6 3135.4,1756.6 3080.4,1796.6 3135.4,1796.6
GND_WSH1: C7.1 C8.2 C34.2 C48.2 C146.1 FB17.1 J6.1 J6.2 J11.2 R23.1 U7.4 | length 775.3
  Top Layer w20: v1@2394.02,1467 C34.2@2436.5,1467 ; C7.1@2462.99,1945 v1(2462.99,2013) 2462.99,2055.99 2486.53,2079.53 FB17.1@2552.99,2079.53 2572.99,2099.53 2572.99,2306 J11.2@2477.99,2401 ; C8.2@2702.99,1945 v1(2702.99,2013) ; v1(2734.49,1143.5) C48.2@2734.49,1186 v1(2734.49,1228.5)
  other v1: 2461.99,1102 2461.99,1154 2392.5,1468.52
GND_XSH1: C10.1 C11.2 C19.1 C45.2 C56.2 FB16.1 J7.1 J7.2 J15.2 R26.1 U11.4 | length 1154.5
  Top Layer w20: v1(6341.94,1099.13) U11.4@6390.45,1099.13 6390.45,1152 6378.01,1164.44 R26.1@6378.01,1196.8 v1(6378.01,1245.3) ; J15.2@6360.45,2350 6445.45,2265 6445.45,2111.5 6420.45,2086.5 FB16.1@6420.45,2084.53
  Top Layer w25: v1(6340.45,1870) C10.1@6340.45,1945 6340.45,2049.53 6375.45,2084.53 FB16.1@6420.45,2084.53 ; v1(6585.45,1875) C11.2@6585.45,1945 ; C45.2@6600.95,1534 v1(6600.95,1589.5) ; v1(6603.43,1141.3) C56.2@6603.43,1196.8 v1(6658.94,1196.8) ; v1(6661.45,1374) 6661.45,1299.21 C19.1@6659.46,1297.22 v1(6714.96,1297.22)
NetC3_2: C3.2 C12.2 D25.3 FB3.2 U5.3 | length 1062.4
  Top Layer w20: D25.3@487,1762 532,1762 533,1763 ; FB3.2@516,2023.5 543.2,1996.3 543.2,1982.2 511,1950 C3.2@511,1945 536,1920 536,1886.5 C12.2@514.5,1865 533,1846.5 533,1763 ; U5.3@525,1102 525,1164 533,1172 533,1763 ; 533,1748 519,1762 533,1776
NetC4_1: C4.1 C12.1 D28.3 FB2.2 U5.2 | length 1055.5
  Top Layer w20: 561,1746 577,1762 561,1778 ; 561,1762 D28.3@606,1762 ; U5.2@575,1102 575,1159 561,1173 561,1848.5 C12.1@577.5,1865 564,1878.5 564,1918 C4.1@591,1945 571.2,1964.8 571.2,2008.7 FB2.2@586,2023.5
NetC5_2: C5.2 C13.2 D31.3 FB5.2 U6.3 | length 1064.4
  Top Layer w20: D31.3@1503,1762 1548,1762 1549,1763 ; FB5.2@1532,2023.5 FB5.2@1533.51,2021.99 ; FB5.2@1537,2025.47 1559.2,2003.27 1559.2,1982.2 1527,1950 C5.2@1527,1945 1552,1920 1552,1886.5 C13.2@1530.5,1865 1549,1846.5 1549,1763 ; U6.3@1541,1102 1541,1164 1549,1172 1549,1763 ; 1549,1748 1535,1762 1549,1776
NetC6_1: C6.1 C13.1 D26.3 FB4.2 U6.2 | length 1059.6
  Top Layer w20: 1577,1746 1593,1762 1577,1778 ; 1577,1762 D26.3@1622,1762 ; U6.2@1591,1102 1591,1159 1577,1173 1577,1848.5 C13.1@1593.49,1865 1580,1878.5 1580,1918 C6.1@1607,1945 1587.2,1964.8 1587.2,2010.67 FB4.2@1602,2025.47 ; FB4.2@1600.48,2021.99 FB4.2@1602,2023.5
NetC7_2: C7.2 C14.2 D34.3 FB17.2 U7.3 | length 1061.9
  Top Layer w20: D34.3@2518.99,1762 2563.99,1762 2564.99,1763 ; FB17.2@2547.99,2023.5 FB17.2@2552.01,2019.49 ; FB17.2@2552.99,2020.47 2574,1999.47 2574,1981.01 2542.99,1950 C7.2@2542.99,1945 2567.99,1920 2567.99,1886.5 C14.2@2546.5,1865 2564.99,1846.5 2564.99,1763 ; U7.3@2556.99,1102 2556.99,1164 2564.99,1172 2564.99,1763 ; 2564.99,1748 2550.99,1762 2564.99,1776
NetC8_1: C8.1 C14.1 D27.3 FB7.2 U7.2 | length 1057.5
  Top Layer w20: 2592.99,1746 2608.99,1762 2592.99,1778 ; 2592.99,1762 D27.3@2637.99,1762 ; U7.2@2606.99,1102 2606.99,1159 2592.99,1173 2592.99,1848.5 C14.1@2609.49,1865 2595.99,1878.5 2595.99,1918 C8.1@2622.99,1945 2603.19,1964.8 2603.19,2010.67 FB7.2@2617.99,2025.47
NetC9_2: C9.2 C15.2 FB1.1 R15.2 U1.1 | length 362.5
  Top Layer w10: U1.1@3793.2,1766.72 3793.2,1802.72 3811.7,1821.22 C15.2@3811.7,1844.72 ; C15.2@3810.2,1844.72 3810.2,1913.23 R15.2@3811.7,1914.72 ; R15.2@3810.2,1914.72 3842.29,1946.81 C9.2@3842.29,2014.72 FB1.1@3842.29,2107.64
NetC10_2: C10.2 C16.2 FB16.2 R29.2 | length 756.4
  Top Layer w20: FB16.2@6420.45,2025.47 6420.45,2023.5 6447.65,1996.3 6447.65,1972.2 C10.2@6420.45,1945 6454.45,1911 6454.45,1884 6433.95,1863.5 C16.2@6433.95,1860 6455.45,1838.5 6455.45,1389.45 6440,1374 R29.2@6440,1329.5
NetC11_1: C11.1 C16.1 FB6.2 U11.2 | length 971
  Top Layer w20: U11.2@6490.45,1099.13 6490.45,1175 6483.45,1182 6483.45,1846.5 C16.1@6496.94,1860 6482.45,1874.5 6482.45,1922 C11.1@6505.45,1945 6475.65,1974.8 6475.65,1998.7 FB6.2@6500.45,2023.5
NetC15_1: C15.1 R14.2 R15.1 U1.2 | length 235
  Top Layer w10: R14.2@3670.2,1914.72 R14.2@3671.7,1914.72 R15.1@3748.7,1914.72 3748.7,1846.22 C15.1@3750.2,1844.72 ; C15.1@3748.7,1844.72 3748.7,1821.22 3767.6,1802.32 U1.2@3767.6,1766.72
NetC17_2: C17.2 C46.1 J26.1 U5.1
  other v1: 607,1240 645,1240
NetC18_2: C18.2 C47.1 J27.1 U6.1
  other v1: 1623,1240 1661,1240
NetC19_2: C19.2 C56.1 J31.1 U11.1
NetC21_1: C21.1 R16.2 U2.3 | length 171.8
  Top Layer w10: R16.2@4328.88,1688.01 C21.1@4328.88,1623.01 4358.4,1623.01 4378.4,1643.01 U2.3@4427.38,1643.01
NetC23_1: C23.1 R17.2 U3.3 | length 171.8
  Top Layer w10: R17.2@4984.19,1678.01 C23.1@4984.19,1613.01 5013.71,1613.01 5033.71,1633.01 U3.3@5082.69,1633.01
NetC25_1: C25.1 R18.2 U4.3 | length 171.8
  Top Layer w10: R18.2@5658,1677.5 C25.1@5658,1612.5 5687.53,1612.5 5707.53,1632.5 U4.3@5756.5,1632.5
NetC27_2: C27.2 U1.6 | length 85.7
  Top Layer w10: U1.6@3742,1613.12 3742,1570.72 3743.04,1570.72 3761.2,1552.56 3761.2,1548.72 C27.2@3770.2,1539.72
NetC37_2: C37.2 C51.2 FB19.2 U8.3 | length 323.8
  Top Layer w15: FB19.2@4442.38,1413.48 4437.38,1408.48 C37.2@4437.38,1338.01 4450.89,1324.5 C51.2@4450.89,1193.01 ; C51.2@4453.39,1195.51 C51.2@4450.89,1193.01 ; U8.3@4459.89,1104.65 4459.89,1159.25 4450.89,1168.25 C51.2@4450.89,1193.01
NetC38_2: C38.2 C51.1 FB18.2 U8.2 | length 321.8
  Top Layer w15: U8.2@4509.89,1104.65 4509.89,1159.25 4518.89,1168.25 4518.89,1193.01 C51.1@4516.38,1195.51 ; C51.1@4513.88,1193.01 4513.88,1319.5 C38.2@4532.38,1338.01 FB18.2@4532.38,1411.51
NetC40_2: C40.2 C53.2 FB21.2 U9.3 | length 328.8
  Top Layer w15: C53.2@5128.7,1195.51 C53.2@5126.19,1193.01 ; FB21.2@5132.67,1422.75 C40.2@5132.69,1337.01 5126.19,1330.51 C53.2@5126.19,1193.01 ; FB21.2@5133.67,1407.5 FB21.2@5134.19,1408.01 ; U9.3@5135.19,1104.65 5135.19,1159.25 5126.19,1168.25 C53.2@5126.19,1193.01
NetC41_2: C41.2 C53.1 FB20.2 U9.2 | length 417.9
  Top Layer w15: U9.2@5185.19,1104.65 5185.19,1159.25 5194.19,1168.25 5194.19,1193.01 C53.1@5191.69,1195.51 ; C53.1@5189.19,1198.01 5189.19,1308.5 C41.2@5217.69,1337.01 FB20.2@5217.67,1422.75 ; C41.2@5217.69,1337.01 FB20.2@5217.67,1422.75
NetC43_2: C43.2 C55.2 FB23.2 U10.3 | length 328.8
  Top Layer w15: U10.3@5801.5,1101.64 5801.5,1156.24 5792.5,1165.24 5792.5,1190 C55.2@5795.01,1192.5 5795.01,1336.01 C43.2@5796.5,1337.5 5796.5,1417.98 FB23.2@5801.5,1422.98
NetC44_2: C44.2 C55.1 FB22.2 U10.2 | length 335.9
  Top Layer w15: U10.2@5851.5,1101.64 5851.5,1156.24 5860.5,1165.24 5860.5,1190 C55.1@5858,1192.5 5858,1309 C44.2@5886.5,1337.5 FB22.2@5886.5,1421.01
NetC48_1: C48.1 C146.2 J22.1 U7.1
  other v1: 2638.99,1240 2676.99,1240
NetC50_1: C50.1 C147.2 J28.1 U8.1
NetC52_1: C52.1 C148.2 J29.1 U9.1
NetC54_1: C54.1 C149.2 J30.1 U10.1
NetC84_2: C84.2 C94.2 FB8.1 R59.2 U17.1
NetC88_2: C88.2 C97.2 FB9.1 R61.2 U19.1 | length 219.1
  Bottom Layer w10: C97.2@913,1875 918,1870 918,1840 925,1833 U19.1@925,1802 ; C97.2@916.5,1876.5 R61.2@916.5,1940 FB9.1@916.5,2010 ; FB9.1@918,2015 916.5,2013.5 FB9.1@916.5,2010 ; FB9.1@918.47,2010 FB9.1@916.5,2010
NetC91_2: C91.2 C99.2 FB10.1 R62.2 U20.1
NetC94_1: C94.1 R59.1 R63.2 U17.2 | length 242.3
  Bottom Layer w10: U17.2@2988.51,1813.6 2988.51,1857.7 3017.4,1886.6 3080.91,1886.6 R63.2@3105.91,1861.6 ; C94.1@3017.4,1893.1 R59.1@3017.4,1951.6
NetC97_1: C97.1 R61.1 R64.2 U19.2 | length 242.3
  Bottom Layer w10: U19.2@950.6,1802 950.6,1846.1 C97.1@979.5,1875 1043,1875 R64.2@1068,1850 ; C97.1@979.5,1881.5 R61.1@979.5,1940
NetC99_1: C99.1 R62.1 R65.2 U20.2 | length 242.3
  Bottom Layer w10: U20.2@1974,1802 1974,1846.1 2002.9,1875 2066.4,1875 R65.2@2091.4,1850 ; C99.1@2002.9,1881.5 R62.1@2002.9,1940
NetC110_2: C110.2 U17.6 | length 139.1
  Bottom Layer w8: U17.6@3016.4,1662 3016.4,1624.4 3026.2,1614.6 3058.2,1614.6 3075.5,1631.9 C110.2@3106.7,1631.9
NetC111_2: C111.2 FB11.1 U18.3 | length 200.8
  Bottom Layer w20: 3582.6,1737.48 U18.3@3602.6,1737.48
  Bottom Layer w25: FB11.1@3492.6,1852.95 3492.6,1779.57 3540.51,1779.57 3582.6,1737.48
NetC113_2: C113.2 FB12.1 U21.3 | length 228.8
  Bottom Layer w10: FB12.1@443,1740.47 443,1650 453,1640 528,1640 538,1630 538,1600 U21.3@543,1600
NetC116_2: C116.2 U19.6 | length 139.1
  Bottom Layer w8: U19.6@976.2,1648.4 976.2,1610.8 986,1601 1018,1601 1035.3,1618.3 C116.2@1066.5,1618.3
NetC117_2: C117.2 FB13.1 U22.3
NetC120_2: C120.2 U20.6 | length 139.1
  Bottom Layer w8: U20.6@1997.2,1648.4 1997.2,1610.8 2007,1601 2039,1601 2056.3,1618.3 C120.2@2087.5,1618.3
NetC121_2: C121.2 FB14.1 U23.3
NetC123_2: C123.2 FB15.1 U24.1 | length 348
  Bottom Layer w20: C123.2@6879.45,1642.09 6887.36,1650 7086,1650 7104.25,1631.75 U24.1@7104.25,1597.76
  Bottom Layer w25: C123.2@6879.45,1642.09 FB15.1@6879.45,1720.47
NetC134_1: C134.1 C144.1 D37.1 R31.2 | length 22.5
  Bottom Layer w12: C144.1@3495.73,1200.26 C144.1@3511.66,1216.18
NetC150_2: C150.2 C154.1 R33.1 R40.2 U25.3 | length 521.3
  Top Layer w20: v1(4092.5,559.5) 4144.01,508 4269,508 v1(4271,510)
  Bottom Layer w20: v1(4092.5,559.5) R40.2@4138,559.5 ; R33.1@4268.5,460 4269.07,460.57 C154.1@4269.07,547 4274.5,552.43 C150.2@4274.5,628 4273,629.5 U25.3@4273,732.07
NetC152_2: C152.2 C155.2 R34.1 R38.1 U25.14 | length 340.3
  Bottom Layer w20: R38.1@4201,1296.5 4261.57,1296.5 C155.2@4273,1307.93 ; R34.1@4271.91,1379 4273.07,1377.84 C155.2@4273.07,1308 C155.2@4273,1307.93 ; U25.14@4273,1115.93 C155.2@4273,1307.93
NetD1_1: D1.1 R1.1 | length 180.4
  Top Layer w10: R1.1@3675.2,2334.72 3645.2,2334.72 3635.2,2344.72 3635.2,2434.72 3650.2,2449.72 D1.1@3675.2,2449.72
NetD2_2: D2.2 R2.1 | length 68.5
  Top Layer w10: R2.1@3745.2,2326.22 D2.2@3745.2,2387.24 D2.2@3745.2,2394.72
NetD3_1: D3.1 R5.1 | length 61.7
  Top Layer w10: R5.1@3095.4,2258.1 3151.38,2258.1 D3.1@3155.4,2254.08
NetD4_1: D4.1 R3.1 | length 61.7
  Top Layer w20: R3.1@1113,2301.5 1168.98,2301.5 D4.1@1173,2297.48
NetD5_1: D5.1 R4.1 | length 60.4
  Top Layer w20: R4.1@2139,2306.5 2139.98,2307.48 D5.1@2199,2307.48
NetD7_2: D7.2 R60.1 | length 146
  Top Layer w25: v1(7014.45,2025) D7.2@7116.97,2025
  Bottom Layer w25: R60.1@6970.94,2025 v1(7014.45,2025)
NetD8_3: D8.3 R6.1 R7.2 R16.1 | length 293.2
  Top Layer w10: R6.1@4264.39,1758.01 4265.89,1756.51 R6.1@4265.89,1753.01 R16.1@4265.89,1688.01 R16.1@4265.89,1683.01 ; R6.1@4265.89,1758.01 4265.89,1848.39 D8.3@4267.5,1850 4301,1883.5 R7.2@4301,1960 ; R6.1@4266.63,1757.26 R6.1@4267.38,1758.01
NetD9_3: D9.3 R9.1 R10.2 R17.1 | length 334.8
  Top Layer w10: R9.1@4919.7,1743.01 4921.19,1741.51 R17.1@4921.19,1678.01 R17.1@4921.19,1668.01 ; R9.1@4921.19,1743.01 D9.3@4921.19,1833.39 4928.67,1833.39 5010,1914.72 R10.2@5010,1960 ; R9.1@4921.94,1742.26 R9.1@4922.69,1743.01
NetD10_3: D10.3 R12.1 R13.2 R18.1 | length 402.9
  Top Layer w10: R18.1@5595.01,1677.5 5595.51,1678.01 R12.1@5595.51,1744.51 ; R12.1@5595.51,1746.01 D10.3@5595.51,1836.39 5684.39,1836.39 5757.52,1909.52 R13.2@5757.52,1962.5
NetD14_2: D14.2 R28.1 | length 57.4
  Top Layer w20: D14.2@403,1586.52 405.01,1584.51 R28.1@405.01,1530
NetD15_2: D15.2 R30.1 | length 57.4
  Top Layer w20: D15.2@1419,1586.52 1421,1584.51 R30.1@1421,1530
NetD16_2: D16.2 R32.1 | length 57.4
  Top Layer w20: D16.2@2434.99,1586.52 D16.2@2437,1584.51 R32.1@2437,1530
NetD29_2: D29.2 D30.1 T1.6 | length 211.3
  Top Layer w25: T1.6@908,1099.84 T1.6@908.16,1100
  Top Layer w32: T1.6@908.16,1100 968,1100 ; v1(968,1075) 968,1100 ; v1(968,1125) 968,1100
  Bottom Layer w25: D29.2@928,1100 943,1100 v1(968,1075) ; v1(968,1125) 983.53,1125 D30.1@1008.53,1100
NetD32_2: D32.2 D33.1 T2.6 | length 161.3
  Top Layer w25: T2.6@1929,1099.84 1988.84,1099.84 1989,1100
  Bottom Layer w25: D32.2@1949,1100 1964,1100 v1(1989,1075) ; v1(1989,1125) 2004.53,1125 D33.1@2029.53,1100
NetD35_2: D35.2 D36.1 T3.6
  other v1: 2960,1095 2955,1135
NetD37_2: D37.2 D38.1 T4.6 | length 169
  Top Layer w25: T4.6@3525.2,1099.57 3525.2,1149.72 3550.2,1174.72
  Bottom Layer w12: 3649.67,1074.72 3675.2,1074.72 v1(3680.2,1079.72)
  Bottom Layer w25: v1@3665.2,1124.72 3690.2,1099.72 3705.73,1099.72
  other v1: 3680.2,1124.72
NetD39_2: D39.2 T5.6 | length 170.6
  Top Layer w25: v1(6724.61,1099.84) T5.6@6849.45,1099.84
  Bottom Layer w25: v1(6724.61,1099.84) 6724.45,1100 D39.2@6769.98,1100
NetD40_2: D40.2 T5.4 | length 175.3
  Top Layer w25: T5.4@7049.45,1099.84 v1(7174.29,1099.84)
  Bottom Layer w25: D40.2@7123.92,1100 7174.13,1100 v1(7174.29,1099.84)
NetFB2_1: FB2.1 J9.1 R20.2 | length 350.4
  Top Layer w20: FB2.1@586,2089.53 569,2106.53 569,2324 J9.1@646,2401
NetFB4_1: FB4.1 J10.1 R22.2 | length 350.4
  Top Layer w20: FB4.1@1602,2089.53 1585,2106.53 1585,2324 J10.1@1662,2401
NetFB6_1: FB6.1 J15.1 | length 310.7
  Top Layer w20: FB6.1@6500.45,2086.5 6473.45,2113.5 6473.45,2263 J15.1@6560.45,2350
NetFB7_1: FB7.1 J11.1 R23.2 | length 355.4
  Top Layer w20: FB7.1@2617.99,2084.53 2600.99,2101.53 2600.99,2324 J11.1@2677.99,2401
NetFB18_1: FB18.1 R21.2 | length 79.1
  Top Layer w15: FB18.1@4532.38,1472.54 4536.85,1477.01 4596.89,1477.01 R21.2@4605.89,1486.01
NetFB20_1: FB20.1 R24.2 | length 70.8
  Top Layer w15: FB20.1@5217.67,1481.8 5218.14,1482.27 R24.2@5286.18,1482.27 R24.2@5284.68,1483.77
NetFB22_1: FB22.1 R27.2 | length 70.8
  Top Layer w15: FB22.1@5886.5,1482.03 5954.53,1482.03 R27.2@5956.5,1484
NetJ12_1: J12.1 R7.1 | length 334.9
  Top Layer w20: R7.1@4301,2040 4301,2290 J12.1@4361,2350
NetJ13_1: J13.1 R10.1 | length 326.6
  Top Layer w20: R10.1@5010,2040 5010,2310 J13.1@5050,2350
NetJ14_1: J14.1 R13.1 | length 326.6
  Top Layer w20: R13.1@5757.52,2042.5 5757.52,2312.5 J14.1@5797.52,2352.5
NetR6_2: R6.2 R21.1 U2.2 U2.6 | length 574
  Top Layer w10: R6.2@4332.38,1753.01 4357.38,1753.01 4372.38,1738.01 4372.38,1703.01 4382.38,1693.01 U2.2@4427.38,1693.01
  Top Layer w12: U2.2@4427.38,1693.01 4487.38,1693.01 4537.38,1643.01 U2.6@4616.38,1643.01 4667.38,1643.01 4687.38,1623.01 4687.38,1504.51 R21.1@4668.88,1486.01
NetR9_2: R9.2 R24.1 U3.2 U3.6 | length 579.4
  Top Layer w10: R9.2@4984.19,1743.01 5012.69,1743.01 5027.69,1728.01 5027.69,1693.01 5037.69,1683.01 U3.2@5082.69,1683.01 5147.69,1683.01 5197.69,1633.01 U3.6@5271.69,1633.01 5332.69,1633.01 5349.19,1616.51 R24.1@5349.19,1475.01
NetR12_2: R12.2 R27.1 U4.2 U4.6 | length 559.5
  Top Layer w10: R12.2@5658,1742.5 5686.5,1742.5 5701.5,1727.5 5701.5,1692.5 5711.5,1682.5 U4.2@5756.5,1682.5 5821.5,1682.5 5871.5,1632.5 U4.6@5945.5,1632.5 ; U4.6@5946.5,1632.5 5996.5,1632.5 6023,1606.01 R27.1@6023,1487.5
NetR25_2: R25.2 U11.6 | length 112.6
  Top Layer w10: R25.2@6410,570 6440.45,600.45 U11.6@6440.45,670
NetR26_2: R26.2 R29.1 U11.3 | length 168
  Top Layer w20: R29.1@6440,1266.5 6440,1197.8 R26.2@6441,1196.8 6441,1099.68 U11.3@6440.45,1099.13
NetR35_1: R35.1 R36.2 TP14.1 | length 288.6
  Bottom Layer w20: R36.2@4463.56,630 4531.5,630 R35.1@4533,628.5 4611.5,707 TP14.1@4719,707
NetR36_1: R36.1 U25.1 | length 116.8
  Bottom Layer w20: U25.1@4373,732.07 4373,665.44 R36.1@4408.44,630
NetR38_2: R38.2 R43.2 U25.13 | length 190.7
  Bottom Layer w20: R43.2@4137,1233.5 R38.2@4201,1233.5 4223,1211.5 U25.13@4223,1115.93
NetR39_1: R39.1 U5.6 | length 98.5
  Top Layer w10: R39.1@526,574 U5.6@526,672.5
NetR40_1: R40.1 TP15.1 U25.5 | length 386.6
  Bottom Layer w15: TP15.1@3937,474 4085.5,622.5 R40.1@4138,622.5 4173,657.5 U25.5@4173,732.07
NetR41_2: R41.2 TP13.1 U25.4 | length 385.2
  Bottom Layer w15: TP13.1@4048,474 4139,474 4176.5,511.5 4176.5,598.87 4205.76,628.13 R41.2@4208,628.13 4223,643.13 U25.4@4223,732.07
NetR42_1: R42.1 U6.6 | length 98.5
  Top Layer w10: R42.1@1542,574 U6.6@1542,672.5
NetR44_1: R44.1 U25.6 U25.7 U25.8 | length 243.6
  Bottom Layer w20: R44.1@4008.56,640 4051,640 4073,662 U25.7@4073,732.07 ; U25.8@4023,732.07 U25.7@4073,732.07 ; U25.6@4123,732.07 U25.7@4073,732.07
NetR45_2: R45.2 U25.10 U25.11 U25.12 | length 203.4
  Bottom Layer w20: R45.2@4065,1216 4073,1208 U25.10@4073,1115.93 U25.11@4123,1115.93 U25.12@4173,1115.93
NetR46_1: R46.1 U7.6 | length 98.5
  Top Layer w10: R46.1@2556.99,574.36 U7.6@2556.99,672.87
NetR48_1: R48.1 U8.6 | length 98.5
  Top Layer w10: R48.1@4459.89,577.01 U8.6@4459.89,675.51
NetR51_1: R51.1 U9.6 | length 98.5
  Top Layer w10: R51.1@5135.19,577.01 U9.6@5135.19,675.51
NetR55_1: R55.1 U10.6 | length 98.5
  Top Layer w10: R55.1@5801.5,574 U10.6@5801.5,672.5
NetR58_1: R58.1 U11.7 | length 106.9
  Top Layer w10: R58.1@6475,569.5 6475,607 6490.45,622.45 U11.7@6490.45,670
NetT1_1: T1.1 U12.3 | length 103.7
  Top Layer w25: T1.1@908,740 941,707 941,691.84 U12.3@970.6,662.24
NetT1_3: T1.3 U12.1 | length 103.7
  Top Layer w25: U12.1@1045.4,662.24 1076,692.84 1076,708 T1.3@1108,740
NetT2_1: T2.1 U13.3 | length 103.7
  Top Layer w25: T2.1@1929,740 1962,707 1962,691.84 U13.3@1991.6,662.24
NetT2_3: T2.3 U13.1 | length 103.7
  Top Layer w25: U13.1@2066.4,662.24 2097,692.84 2097,708 T2.3@2129,740
NetT3_1: T3.1 U14.3 | length 119.9
  Top Layer w25: T3.1@2915,760 2963,712 2963,701.84 U14.3@2992.59,672.24
NetT3_3: T3.3 U14.1 | length 107.5
  Top Layer w25: U14.1@3067.4,672.24 3067.4,712.4 T3.3@3115,760
NetT4_1: T4.1 U15.3 | length 103.7
  Top Layer w25: T4.1@3515.2,739.72 3548.2,706.72 3548.2,691.57 U15.3@3577.8,661.97
NetT4_3: T4.3 U15.1 | length 103.7
  Top Layer w25: U15.1@3652.6,661.97 3683.2,692.57 3683.2,707.72 T4.3@3715.2,739.72
NetT5_1: T5.1 U16.3 | length 103.7
  Top Layer w25: T5.1@6849.45,740 6882.45,707 6882.45,691.84 U16.3@6912.05,662.24
NetT5_3: T5.3 U16.1 | length 103.7
  Top Layer w25: U16.1@6986.85,662.24 7012.45,687.84 7012.45,703 T5.3@7049.45,740
NEUTRAL: J12.2 J13.2 J14.2 R8.1 R11.1 R19.1 | length 990.1
  Top Layer w20: J12.2@4161,2350 4206,2305 R8.1@4206,2040 ; J13.2@4850,2350 4900,2300 R11.1@4900,2040 ; J14.2@5597.52,2352.5 5647.52,2302.5 R19.1@5647.52,2042.5
pads on no net: FID1.1 FID2.1 FID3.1 FID4.1 FID5.1 FID6.1 FID7.1 FID8.1 LBL1.0 MH1.1 MH2.1 MH3.1 MH4.1 T1.5 T2.5 T3.5 T4.5 U1.7 U2.1 U2.5 U2.8 U3.1 U3.5 U3.8 U4.1 U4.5 U4.8 U17.7 U18.4 U18.5 U19.7 U20.7 U21.4 U21.5 U22.4 U22.5 U23.4 U23.5

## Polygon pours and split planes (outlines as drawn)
NEUTRAL on MidLayer1 "g" (solid, remove dead copper, pour order 209): 4886.68,2315 4824,2315 4810.27,2328.73 4810.27,2418.59 4785.87,2443 4216,2443 4202,2429 4197,2424 4197,2350 4197,2333 4179,2315 4106,2315 4092,2329 4092,2497.48 4102,2507.48 4104.11,2509.59 4170.27,2509.59 5612.41,2509.59 5635,2487 5635,2351 5635,2328 5623,2316 5569,2316 5560,2325 5560,2423 5540,2443 5383.87,2443 4914.69,2443 4896.27,2424.59 4896.27,2324.59
GND_PH on MidLayer1 "g" (solid, remove dead copper, pour order 205): 6190,1095 6158.5,1063.5 3552.99,1063.5 3475.2,1141.3 3430.2,1186.3 3430.2,1844.72 3430.2,2476.2 3454,2500 3802,2500 3813,2489 3832,2470 3832,2370 3832,2290 3856,2266 4125,1997 6155,1997 6190.17,1961.84
GND_USH on MidLayer1 "g" (solid, remove dead copper, pour order 203): 1182.01,2500 819.01,2500 809.01,2490 806.01,2487 806.01,2366 806.01,2101 785.01,2080 330.01,2080 306.01,2056 296.01,2046 296.01,1815 296.01,1311 388.01,1219 403,1204.01 403,1170 403,1079 412,1070 1068,1070 1213,1215 1213,2469
GND_VSH on MidLayer1 "g" (solid, remove dead copper, pour order 199): 2198,2500 1835,2500 1825,2490 1822,2487 1822,2366 1822,2101 1801,2080 1346,2080 1322,2056 1312,2046 1312,1815 1312,1311 1404,1219 1419,1204.01 1419,1170 1419,1079 1428,1070 2084,1070 2229,1215 2229,2469
GND_WSH on MidLayer1 "g" (solid, remove dead copper, pour order 195): 3214,2500 2851,2500 2841,2490 2838,2487 2838,2366 2838,2101 2817,2080 2362,2080 2338,2056 2328,2046 2328,1815 2328,1311 2420,1219 2434.99,1204.01 2434.99,1170 2434.99,1079 2443.99,1070 3100,1070 3245,1215 3245,2469
GND_XSH1 on MidLayer1 "g" (solid, remove dead copper, pour order 189): 6780,2370 6724,2370 6721,2367 6721,2047 6671,1997 6340,1997 6322,1979 6306.45,1963.45 6306.45,1117.55 6360.5,1063.5 6728.21,1063.5 6744.58,1079.87 6744.58,1625.58 6791,1672 6800,1681 6800,2232 6800,2359 6789,2370
GND_VDC on MidLayer1 "g" (solid, remove dead copper, pour order 187): 6824,2353 6824,1681 6759,1616 6759,1070 6765.5,1063.5 7183.5,1063.5 7215,1095 7236,1116 7236,1166 7236,2078 6944,2370 6841,2370
+3.3V_DVDD on MidLayer1 "g" (solid, remove dead copper, pour order 173): 45,554.53 45,762 67,784 7211,784 7234,761 7234,92 7188,46 93,46 46,93 45,94 45,550.05
NEUTRAL on MidLayer2 "g" (solid, remove dead copper, pour order 211): 4886.68,2315 4824,2315 4810.27,2328.73 4810.27,2418.59 4785.87,2443 4216,2443 4202,2429 4197,2424 4197,2350 4197,2333 4179,2315 4106,2315 4092,2329 4092,2497.48 4102,2507.48 4104.11,2509.59 4170.27,2509.59 5612.41,2509.59 5635,2487 5635,2351 5635,2328 5623,2316 5569,2316 5560,2325 5560,2423 5540,2443 5383.87,2443 4914.69,2443 4896.27,2424.59 4896.27,2324.59
GND_USH1 on MidLayer2 "g" (solid, remove dead copper, pour order 201): 1182.01,2500 819.01,2500 809.01,2490 806.01,2487 806.01,2366 806.01,2101 785.01,2080 330.01,2080 306.01,2056 296.01,2046 296.01,1815 296.01,1311 388.01,1219 403,1204.01 403,1170 403,1079 412,1070 1068,1070 1213,1215 1213,2469
GND_VSH1 on MidLayer2 "g" (solid, remove dead copper, pour order 197): 2198,2500 1835,2500 1825,2490 1822,2487 1822,2366 1822,2101 1801,2080 1346,2080 1322,2056 1312,2046 1312,1815 1312,1311 1404,1219 1419,1204.01 1419,1170 1419,1079 1428,1070 2084,1070 2229,1215 2229,2469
